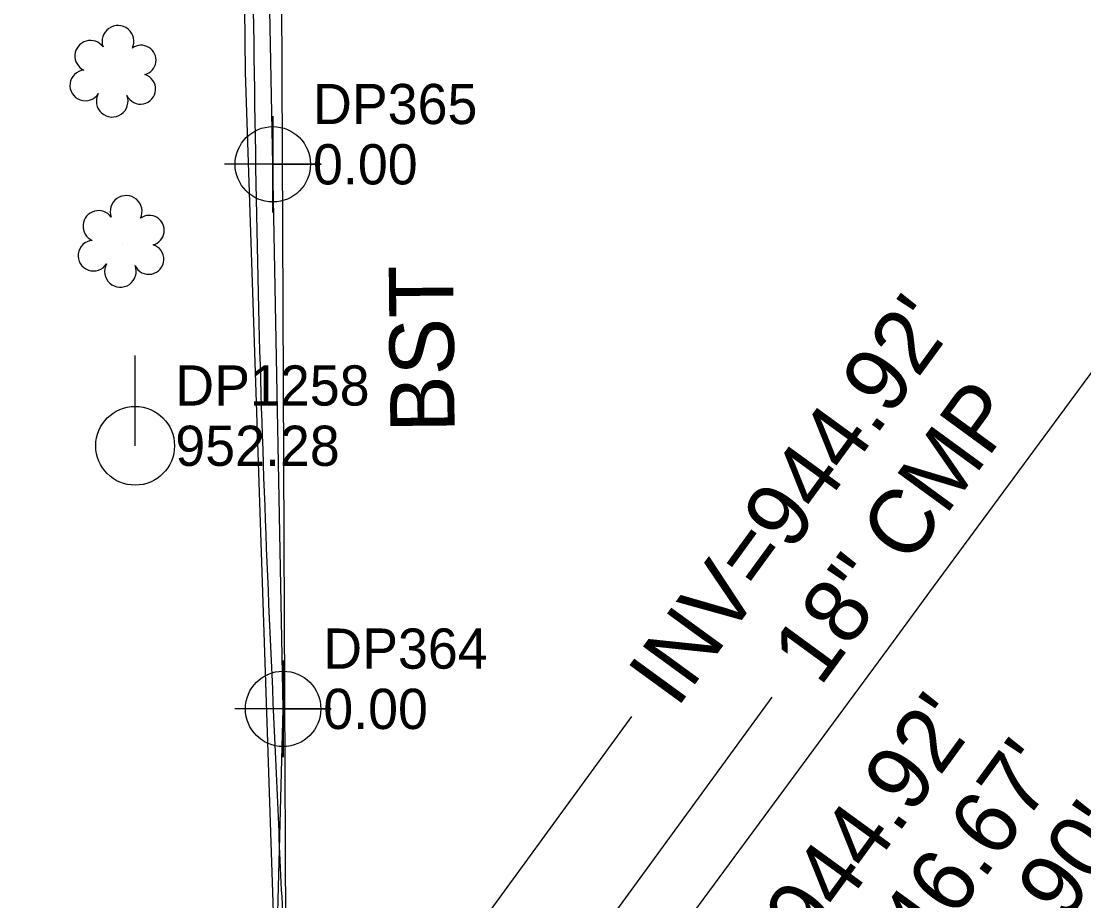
# Model space of a CAD drawing. Extents: x 1182322 to 1186765, y 572295 to 575411.
# Drawn here: x 1183866.3 to 1183932.4, y 573283.9 to 573338.6 of the extents above; entities that cross this region are included whole.
import ezdxf

# ---------------------------------------------------------------- set-up
doc = ezdxf.new("R2010")
doc.units = 0
for name, color, linetype in [('Exist Other Culture Fence Line', 7, 'Continuous'), ('Exist Property Line', 7, 'Continuous'), ('Exist Right of Way Line', 7, 'Continuous'), ('Exist Roads EOP', 7, 'Continuous'), ('Exist Roads EOP Other Text', 7, 'Continuous'), ('Exist Structure Minor Drop Inlet Top Elevation', 7, 'Continuous'), ('Exist Structure Minor Pipes CMP 15 Inch Invert', 7, 'Continuous'), ('Exist Structure Minor Pipes CMP 18 Inch Invert', 7, 'Continuous'), ('Exist Structure Minor Pipes CMP 18 Inch Text', 7, 'Continuous'), ('Exist Utilities Power Pole CELL', 7, 'Continuous'), ('Exist Utilities Power Pole Cogo Elevation', 7, 'Continuous'), ('Exist Utilities Power Pole Cogo Number', 7, 'Continuous'), ('Exist Utilities Telephone UG FO SUE LOS C', 7, 'Continuous'), ('Exist Utilities Telephone UG FO SUE LOS C Cogo Elevation', 7, 'Continuous'), ('Exist Utilities Telephone UG FO SUE LOS C Cogo Number', 7, 'Continuous'), ('Exist Utilities Telephone UG FO SUE LOS C Cogo Point CELL', 7, 'Continuous'), ('Exist Vegetation Shrub CELL', 7, 'Continuous')]:
    doc.layers.add(name, color=color, linetype=linetype)

msp = doc.modelspace()

# ---------------------------------------------------------------- linework, layer by layer
at = {"layer": 'Exist Other Culture Fence Line'}
msp.add_lwpolyline([(1183875.706, 573269.13), (1183882.281, 573274.5), (1183880.264, 573335.479), (1183879.942, 573365.545), (1183879.147, 573405.433), (1183879.443, 573440.932), (1183879.29, 573466.248), (1183879.454, 573496.478), (1183879.147, 573519.038), (1183879.392, 573536.929)], dxfattribs=at)
at = {"layer": 'Exist Property Line'}
msp.add_line((1183882.9, 573249.002), (1183880.082, 573905.178), dxfattribs=at)
at = {"layer": 'Exist Right of Way Line'}
msp.add_line((1183782.141, 573112.288), (1183920.542, 573300.076), dxfattribs=at)
msp.add_arc((1124762.272, 616900.028), 73489.16, 323.60959292, 324.03100952, dxfattribs=at)
at = {"layer": 'Exist Roads EOP'}
msp.add_spline([(1183888.111, 573234.75), (1183887.266, 573239.862), (1183885.398, 573251.839), (1183884.594, 573257.847), (1183883.92, 573263.875), (1183882.827, 573278.308), (1183882.139, 573292.763), (1183881.535, 573306.754), (1183881.086, 573320.75), (1183880.571, 573351.991), (1183880.026, 573376.469)], degree=3, dxfattribs=at)
at = {"layer": 'Exist Structure Minor Pipes CMP 18 Inch Invert'}
for points in [[(1183902.516, 573227.677), (1183897.149, 573274.868), (1183912.997, 573296.612)], [(1183901.63, 573228.102), (1183892.395, 573279.102), (1183904.279, 573295.408)]]:
    msp.add_lwpolyline(points, dxfattribs=at)
at = {"layer": 'Exist Utilities Power Pole CELL'}
for q in [(1183873.389, 573317.868), (1183873.389, 573312.243)]:
    msp.add_line((1183873.389, 573312.243), q, dxfattribs=at)
msp.add_circle((1183873.389, 573312.243), 2.45, dxfattribs=at)
at = {"layer": 'Exist Utilities Telephone UG FO SUE LOS C'}
msp.add_lwpolyline([(1183831.197, 573051.404), (1183831.988, 573067.671), (1183835.941, 573100.343), (1183843.81, 573135.412), (1183849.422, 573158.282), (1183872.211, 573240.171), (1183881.951, 573271.332), (1183882.592, 573295.878), (1183881.953, 573329.75), (1183881.173, 573370.193), (1183880.739, 573416.085), (1183881.105, 573461.728), (1183880.375, 573505.494), (1183880.228, 573551.998), (1183881.563, 573597.965), (1183880.769, 573642.039), (1183880.144, 573689.544)], dxfattribs=at)
at = {"layer": 'Exist Utilities Telephone UG FO SUE LOS C Cogo Point CELL'}
for points in [[(1183881.953, 573332.75), (1183881.953, 573326.75), (1183881.953, 573329.75), (1183884.953, 573329.75), (1183878.953, 573329.75)], [(1183882.592, 573298.878), (1183882.592, 573292.878), (1183882.592, 573295.878), (1183885.592, 573295.878), (1183879.592, 573295.878)]]:
    msp.add_lwpolyline(points, dxfattribs=at)
for centre in [(1183881.953, 573329.75), (1183882.592, 573295.878)]:
    msp.add_circle(centre, 2.344, dxfattribs=at)
at = {"layer": 'Exist Vegetation Shrub CELL'}
for p, q in [((1183872.093, 573335.357), (1183872.093, 573335.357)), ((1183872.603, 573324.774), (1183872.603, 573324.774))]:
    msp.add_line(p, q, dxfattribs=at)
for centre, radius, start, end in [((1183872.321, 573337.397), 0.99, 334.83907, 200.47174), ((1183870.61, 573336.484), 0.968, 35.89076, 245.42165), ((1183873.765, 573336.226), 0.929, 284.45672, 126.08612), ((1183870.292, 573334.652), 0.955, 95.10992, 327.95341), ((1183873.73, 573334.428), 0.937, 204.99133, 73.46012), ((1183871.964, 573333.673), 0.984, 151.27966, 21.38702), ((1183872.832, 573326.814), 0.99, 334.83907, 200.47174), ((1183871.12, 573325.901), 0.968, 35.89076, 245.42165), ((1183874.275, 573325.643), 0.929, 284.45672, 126.08612), ((1183870.803, 573324.069), 0.955, 95.10992, 327.95341), ((1183874.24, 573323.845), 0.937, 204.99133, 73.46012), ((1183872.475, 573323.09), 0.984, 151.27966, 21.38702)]:
    msp.add_arc(centre, radius, start, end, dxfattribs=at)

# ---------------------------------------------------------------- texts
at = {"layer": 'Exist Roads EOP Other Text'}
msp.add_text('BST', height=4, rotation=90.56271, dxfattribs=at).set_placement((1183893.263, 573313.07))
at = {"layer": 'Exist Structure Minor Drop Inlet Top Elevation'}
msp.add_text("TOP=946.67'", height=4, rotation=53.91567, dxfattribs=at).set_placement((1183912.543, 573266.559))
at = {"layer": 'Exist Structure Minor Pipes CMP 15 Inch Invert'}
msp.add_text("INV=944.90'", height=4, rotation=53.91567, dxfattribs=at).set_placement((1183917.993, 573264.366))
at = {"layer": 'Exist Structure Minor Pipes CMP 18 Inch Invert'}
for p in [(1183907.073, 573295.847), (1183908.441, 573271.082)]:
    msp.add_text("INV=944.92'", height=4, rotation=53.91567, dxfattribs=at).set_placement(p)
at = {"layer": 'Exist Structure Minor Pipes CMP 18 Inch Text'}
msp.add_text('18" CMP', height=4, rotation=53.81792, dxfattribs=at).set_placement((1183915.99, 573297.188))
at = {"layer": 'Exist Utilities Power Pole Cogo Elevation'}
msp.add_text('952.28', height=2.5, dxfattribs=at).set_placement((1183875.889, 573310.993))
at = {"layer": 'Exist Utilities Power Pole Cogo Number'}
msp.add_text('DP1258', height=2.5, dxfattribs=at).set_placement((1183875.889, 573314.743))
at = {"layer": 'Exist Utilities Telephone UG FO SUE LOS C Cogo Elevation'}
for p in [(1183884.453, 573328.5), (1183885.092, 573294.628)]:
    msp.add_text('0.00', height=2.5, dxfattribs=at).set_placement(p)
at = {"layer": 'Exist Utilities Telephone UG FO SUE LOS C Cogo Number'}
for s, p in [('DP365', (1183884.453, 573332.25)), ('DP364', (1183885.092, 573298.378))]:
    msp.add_text(s, height=2.5, dxfattribs=at).set_placement(p)

doc.saveas('drawing.dxf')
